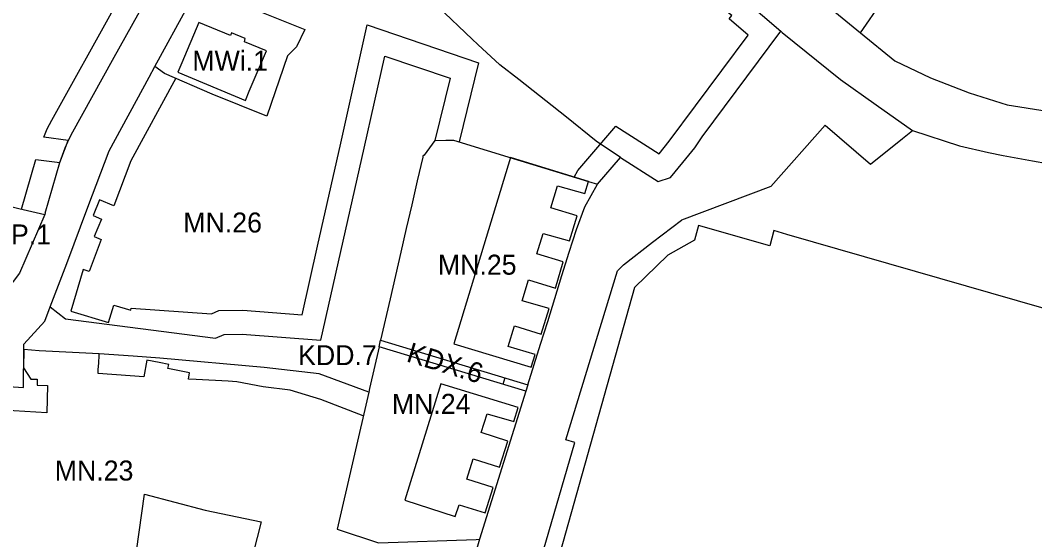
# Model space of a CAD drawing. Extents: x 7419601 to 7420547, y 5548907 to 5549873.
# Drawn here: x 7419779.2 to 7420033.1, y 5549396.6 to 5549526.6 of the extents above; entities that cross this region are included whole.
import ezdxf

# ---------------------------------------------------------------- set-up
doc = ezdxf.new("R2010")
doc.units = 0
for name, color, linetype in [('LIN_linie_rozgraniczajace', 7, 'Continuous'), ('LIN_nieprzekraczalna linia zabudowy', 7, 'Continuous'), ('LIN_obowiązująca linia zabudowy', 7, 'Continuous'), ('TXT_opisy_przeznaczen', 7, 'Continuous')]:
    doc.layers.add(name, color=color, linetype=linetype)

msp = doc.modelspace()

# ---------------------------------------------------------------- linework, layer by layer
at = {"layer": 'LIN_linie_rozgraniczajace'}
for p, q in [((7419780.14, 5549445.53), (7419785.36, 5549451.26)), ((7419905.78, 5549433.7), (7419894.15, 5549396.71))]:
    msp.add_line(p, q, dxfattribs=at)
for points in [[(7419866.67, 5549612.69), (7419870.51, 5549609.89), (7419877.12, 5549603.54), (7419886.7, 5549595.06), (7419892.42, 5549590.02), (7419901.31, 5549582.26), (7419969.59, 5549523.82)], [(7419792.38, 5549498.69), (7419802.33, 5549516.61), (7419810.63, 5549531.56), (7419818.93, 5549546.5), (7419824.16, 5549555.93), (7419835.42, 5549586.49), (7419838.7, 5549594.38)], [(7419989.52, 5549523.43), (7419994.93, 5549531.32), (7419995.84, 5549530.7), (7419998.38, 5549534.49), (7419997.5, 5549535.08), (7419999.15, 5549537.48), (7419995.93, 5549541.49), (7419990.06, 5549553.81), (7419993.56, 5549556.15), (7419989.25, 5549562.64), (7419977.37, 5549571.35), (7419970.03, 5549577.66), (7419951.57, 5549582.76), (7419932.51, 5549586.98), (7419930.57, 5549587.41), (7419930.61, 5549584.15), (7419924.89, 5549576.71), (7419924.49, 5549576.19)], [(7419924.89, 5549576.71), (7419944.52, 5549560.18), (7419955.3, 5549551.19), (7419963.04, 5549544.9), (7419980.36, 5549530.97), (7419989.52, 5549523.43)], [(7419929.48, 5549492.2), (7419923.36, 5549496.34), (7419915.97, 5549502.3), (7419904.02, 5549511.77), (7419899.22, 5549515.43), (7419893.74, 5549520.56), (7419892.37, 5549521.85), (7419875.12, 5549538.31), (7419870.06, 5549543.14), (7419857.57, 5549554.7), (7419856.13, 5549556.04), (7419856.77, 5549558.74), (7419837.53, 5549563.26)], [(7419823.39, 5549534.11), (7419828.68, 5549532.39), (7419835.8, 5549530.09), (7419850.45, 5549524.3), (7419848.32, 5549519.98), (7419846.12, 5549517.67), (7419840.96, 5549502.57), (7419827.22, 5549508.13), (7419815.32, 5549513.23), (7419812.9, 5549514.98)], [(7419812.9, 5549514.98), (7419821.49, 5549530.74), (7419823.39, 5549534.11)], [(7419929.48, 5549492.2), (7419938.87, 5549486.22), (7419941.99, 5549487.26), (7419945.08, 5549491.02), (7419948.1, 5549494.69), (7419949.94, 5549497.39), (7419969.59, 5549523.82)], [(7419969.59, 5549523.82), (7419969.92, 5549523.54), (7419984.5, 5549511.75)], [(7419989.52, 5549523.43), (7419998.15, 5549516.44), (7420007.04, 5549512.18), (7420016.72, 5549508.44), (7420026.26, 5549505.43), (7420036.29, 5549503.84), (7420042.96, 5549509.97), (7420115.64, 5549502.24), (7420186.48, 5549494.96), (7420230.69, 5549490.47), (7420266.36, 5549486.86), (7420280.44, 5549485.21), (7420290.37, 5549484.05), (7420314.5, 5549481.58), (7420318.73, 5549480.82), (7420355.46, 5549476.76), (7420369.45, 5549475.22), (7420400.67, 5549471.75), (7420403.92, 5549471.39)], [(7419786.7, 5549454.82), (7419790.53, 5549451.88), (7419828.12, 5549447.01), (7419830.21, 5549447.93), (7419834.73, 5549448.03), (7419854.48, 5549446.51), (7419859.48, 5549468.73), (7419865.28, 5549494.53), (7419870.47, 5549517.63), (7419886.81, 5549512.06)], [(7419785.36, 5549451.26), (7419786.7, 5549454.82), (7419790.83, 5549465.7), (7419796.11, 5549479.79), (7419801.43, 5549493.89), (7419811.46, 5549512.32), (7419812.9, 5549514.98)], [(7419886.81, 5549512.06), (7419882.98, 5549496.49), (7419880.3, 5549492.78), (7419880, 5549492.57), (7419879.94, 5549492.28), (7419878.59, 5549486.42), (7419877.21, 5549480.42), (7419875.84, 5549474.42), (7419874.49, 5549468.56), (7419873.14, 5549462.7), (7419871.8, 5549456.84), (7419869.41, 5549446.49)], [(7419984.5, 5549511.75), (7419993.49, 5549505.39), (7420002.51, 5549498.99), (7420014.32, 5549495.14), (7420021.61, 5549493.48), (7420025.26, 5549492.77), (7420032.62, 5549491.41), (7420036.32, 5549490.76), (7420040.04, 5549490.26), (7420043.75, 5549489.76), (7420062.82, 5549488.99)], [(7419772.86, 5549501.2), (7419775.41, 5549499), (7419774.83, 5549493.83), (7419773.35, 5549480.78), (7419778.88, 5549479.48), (7419785.33, 5549477.97)], [(7419785.45, 5549478.26), (7419789.1, 5549490.97), (7419790.15, 5549493.74), (7419790.49, 5549494.64), (7419791.45, 5549496.94), (7419792.38, 5549498.69)], [(7419980.7, 5549500.37), (7419967.1, 5549484.98), (7419944.7, 5549476.57)], [(7419980.7, 5549500.37), (7419992.02, 5549490.59), (7420000.09, 5549496.98), (7420002.51, 5549498.99)], [(7419882.98, 5549496.49), (7419885.7, 5549496.56), (7419887.65, 5549496.61), (7419904.54, 5549491.42), (7419921.44, 5549486.23), (7419923.72, 5549485.53)], [(7419906.29, 5549435.33), (7419909.46, 5549445.49), (7419911.24, 5549451.22), (7419913.02, 5549456.95), (7419914.81, 5549462.67), (7419916.65, 5549468.54), (7419918.41, 5549474.2), (7419920.57, 5549479.89), (7419923.72, 5549485.53), (7419929.48, 5549492.2)], [(7419785.45, 5549478.26), (7419785.33, 5549477.97), (7419779.01, 5549463.24), (7419773.89, 5549456.66)], [(7419903.11, 5549369.61), (7419918, 5549420.91), (7419915.74, 5549421.56), (7419928.75, 5549463.85), (7419929.6, 5549464.8), (7419930.22, 5549465.38), (7419937.48, 5549471), (7419944.7, 5549476.57)], [(7419751.74, 5549427), (7419757.74, 5549433.05), (7419759.68, 5549434.46), (7419761.59, 5549435.87), (7419772.43, 5549435.18), (7419779.99, 5549434.69), (7419780.12, 5549444.2), (7419780.14, 5549445.53)], [(7419869.04, 5549444.83), (7419869.41, 5549446.49)], [(7419869.41, 5549446.49), (7419906.29, 5549435.33)], [(7419866.43, 5549433.49), (7419854.04, 5549438.1), (7419840.28, 5549439.64), (7419814.13, 5549441.96), (7419807.51, 5549442.49), (7419798.94, 5549443.09), (7419783.92, 5549443.86), (7419780.12, 5549444.2)], [(7419869.04, 5549444.83), (7419866.64, 5549434.44), (7419866.43, 5549433.49)], [(7419905.78, 5549433.7), (7419869.04, 5549444.83)], [(7419906.29, 5549435.33), (7419905.78, 5549433.7)], [(7419866.43, 5549433.49), (7419858.54, 5549399.2), (7419868.91, 5549395.8), (7419893.34, 5549396.57), (7419894.15, 5549396.71)], [(7419806.26, 5549378.83), (7419810.27, 5549407.94), (7419825.48, 5549403.94), (7419839.54, 5549401.03), (7419832.39, 5549373.24), (7419831.86, 5549369.96)], [(7419894.15, 5549396.71), (7419890.95, 5549385.44), (7419885.34, 5549366.2), (7419883.76, 5549361.41)]]:
    msp.add_lwpolyline(points, dxfattribs=at)
at = {"layer": 'LIN_nieprzekraczalna linia zabudowy'}
for p, q in [((7419932.96, 5549459.71), (7419909.37, 5549375.84)), ((7419900.05, 5549435.49), (7419900.56, 5549437.12))]:
    msp.add_line(p, q, dxfattribs=at)
for points in [[(7419917.85, 5549487.33), (7419918.78, 5549488.99), (7419928.33, 5549500.05), (7419939.1, 5549493.19), (7419941.66, 5549496.31), (7419961.43, 5549522.9), (7419956.67, 5549526.98), (7419957.33, 5549527.78), (7419949.59, 5549533.78), (7419949.24, 5549533.34), (7419897.39, 5549577.72), (7419894.99, 5549579.82), (7419897.92, 5549583.55), (7419883.95, 5549594.54), (7419879.16, 5549598.29), (7419877.23, 5549595.94), (7419877.05, 5549596.11), (7419872.74, 5549600.12), (7419866.91, 5549605.07), (7419870.51, 5549609.89)], [(7419779.51, 5549479.33), (7419783.08, 5549491.74), (7419789.1, 5549490.97), (7419791.19, 5549496.51), (7419785.14, 5549497.29), (7419785.98, 5549499.44), (7419785.97, 5549499.42), (7419787.11, 5549501.56), (7419818.69, 5549558.44)], [(7419791.88, 5549453.75), (7419801.33, 5549450.94), (7419802.63, 5549455.23), (7419806.86, 5549454), (7419807.01, 5549454.48), (7419827.06, 5549453.1), (7419828.88, 5549453.9), (7419834.89, 5549454.04), (7419849.76, 5549452.89), (7419853.63, 5549470.05), (7419859.43, 5549495.85), (7419866.08, 5549525.47), (7419893.95, 5549515.97)], [(7419893.95, 5549515.97), (7419889.08, 5549496.17)], [(7419818.17, 5549512.11), (7419806.89, 5549491.39), (7419802.65, 5549480.11)], [(7419802.65, 5549480.11), (7419799.06, 5549481.67), (7419797.43, 5549477.69), (7419799.54, 5549476.83), (7419797.7, 5549472.42), (7419799.48, 5549471.69)], [(7420041.63, 5549452.68), (7419971.07, 5549472.96), (7419967.82, 5549473.94), (7419966.83, 5549470.09), (7419949, 5549475.18), (7419947.96, 5549471.52)], [(7419799.48, 5549471.69), (7419796.49, 5549463.71)], [(7419947.96, 5549471.52), (7419941.34, 5549467.81), (7419932.96, 5549459.71)], [(7419796.49, 5549463.71), (7419794.97, 5549464.16), (7419791.88, 5549453.75)], [(7419865.07, 5549427.58), (7419854.47, 5549431.68), (7419846.74, 5549433.98), (7419839.99, 5549434.81), (7419833.44, 5549436.09), (7419831.25, 5549436.21), (7419823.22, 5549436.65), (7419821.3, 5549436.75), (7419821.57, 5549438.31), (7419816.17, 5549439.4), (7419816.38, 5549440.43), (7419814, 5549440.88), (7419810.9, 5549441.46), (7419810.14, 5549437.36), (7419806.72, 5549437.55), (7419798.7, 5549438.15), (7419798.75, 5549439.09), (7419798.84, 5549440.86), (7419798.94, 5549442.63), (7419798.94, 5549443.09), (7419783.92, 5549443.86), (7419780.12, 5549444.2), (7419780.06, 5549439.56)], [(7419780.06, 5549439.56), (7419781.87, 5549436.77), (7419783.47, 5549436.78), (7419783.43, 5549435.28), (7419786, 5549435.19)], [(7419786, 5549435.19), (7419785.9, 5549428.29), (7419772.05, 5549429.19), (7419763.39, 5549429.74), (7419761.85, 5549428.59), (7419758.12, 5549428.58), (7419758.11, 5549425.04), (7419755.91, 5549422.92)]]:
    msp.add_lwpolyline(points, dxfattribs=at)
at = {"layer": 'LIN_obowiązująca linia zabudowy'}
for points in [[(7419823.87, 5549526.02), (7419819.64, 5549515.91), (7419818.66, 5549513.56), (7419835.57, 5549506.51), (7419836.55, 5549508.85), (7419840.84, 5549518.97), (7419835.31, 5549521.23), (7419835.54, 5549521.99), (7419832.11, 5549523.47), (7419831.8, 5549522.74)], [(7419901.95, 5549492.22), (7419887.72, 5549445.59), (7419907.13, 5549439.71), (7419908.14, 5549442.93), (7419901.34, 5549444.96), (7419902.9, 5549450.1), (7419909.64, 5549448), (7419911.57, 5549454.46), (7419904.88, 5549456.39), (7419906.45, 5549461.58), (7419913.19, 5549459.55), (7419915.12, 5549466.08), (7419908.48, 5549468.15), (7419910.09, 5549473.21), (7419916.69, 5549471.36), (7419918.61, 5549477.65), (7419912.03, 5549479.64), (7419913.73, 5549485.18), (7419920.54, 5549483.19), (7419921.44, 5549486.23)], [(7419888.08, 5549402.37), (7419889.07, 5549405.31), (7419895.56, 5549403.32), (7419897.58, 5549409.66), (7419891.01, 5549411.69), (7419892.56, 5549416.76), (7419899.19, 5549414.69), (7419901.27, 5549421.25), (7419894.58, 5549423.39), (7419896.07, 5549428.08), (7419902.77, 5549426.14), (7419903.83, 5549429.66), (7419884.52, 5549435.57), (7419875.51, 5549406.43)]]:
    msp.add_lwpolyline(points, close=True, dxfattribs=at)

# ---------------------------------------------------------------- texts
at = {"layer": 'TXT_opisy_przeznaczen'}
for s, p in [('MWi.1', (7419822.28, 5549513.94)), ('MN.26', (7419820.02, 5549473.46)), ('ZP.1', (7419772.81, 5549470.47)), ('MN.25', (7419883.75, 5549462.9)), ('KDD.7', (7419848.76, 5549440.25)), ('MN.24', (7419872.22, 5549428.06)), ('MN.23', (7419787.84, 5549411.37))]:
    msp.add_text(s, height=5, dxfattribs=at).set_placement(p)
msp.add_text('KDX.6', height=5, rotation=343, dxfattribs=at).set_placement((7419875.62, 5549441.25))

doc.saveas('drawing.dxf')
